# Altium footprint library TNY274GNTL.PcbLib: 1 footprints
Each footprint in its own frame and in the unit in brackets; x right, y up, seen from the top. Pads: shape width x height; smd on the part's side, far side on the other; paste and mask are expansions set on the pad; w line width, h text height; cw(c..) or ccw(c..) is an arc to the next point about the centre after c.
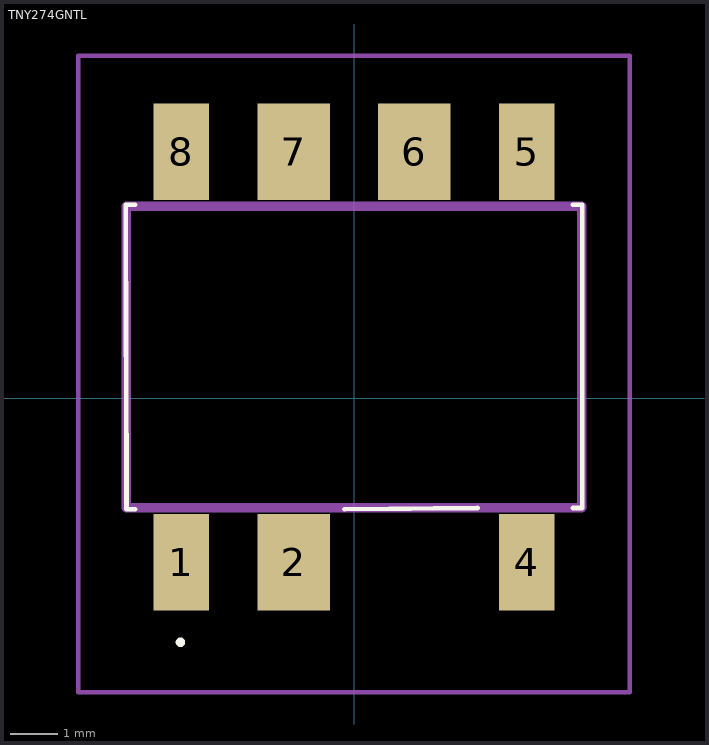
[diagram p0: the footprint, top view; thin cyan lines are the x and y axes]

## TNY274GNTL [mil]
pads (7):
  rect 45.98x80 smd: 1(-142.99,-135.91) 4(142.99,-135.91) 5(142.99,204.09) 8(-142.99,204.09)
  rect 60x80 smd: 2(-50,-135.91) 6(50,204.09) 7(-50,204.09)
Top Overlay:
  lines w3.94: -181.1,-91.89 -188.46,-91.89 -188.98,160.08 -181.1,160.08 ; -7.87,-91.89 102.36,-90.91 ; 181.1,-90.91 188.98,-90.91 188.98,160.08 181.1,160.08 ; -145.67,-202.13 cw(c-143.7,-202.13) -141.73,-202.13 ; -145.67,-202.13 -145.67,-202.13 ; -145.67,-202.13 ccw(c-143.7,-202.13) -141.73,-202.13 ; -141.73,-202.13 -141.73,-202.13
Mechanical 15:
  lines w7.87: -188.46,-90.91 188.46,-90.91 188.46,159.09 -188.46,159.09 -188.46,-90.91
Mechanical 20:
  lines w3.94: -228.35,-243.46 228.35,-243.46 228.35,283.46 -228.35,283.46 -228.35,-243.46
